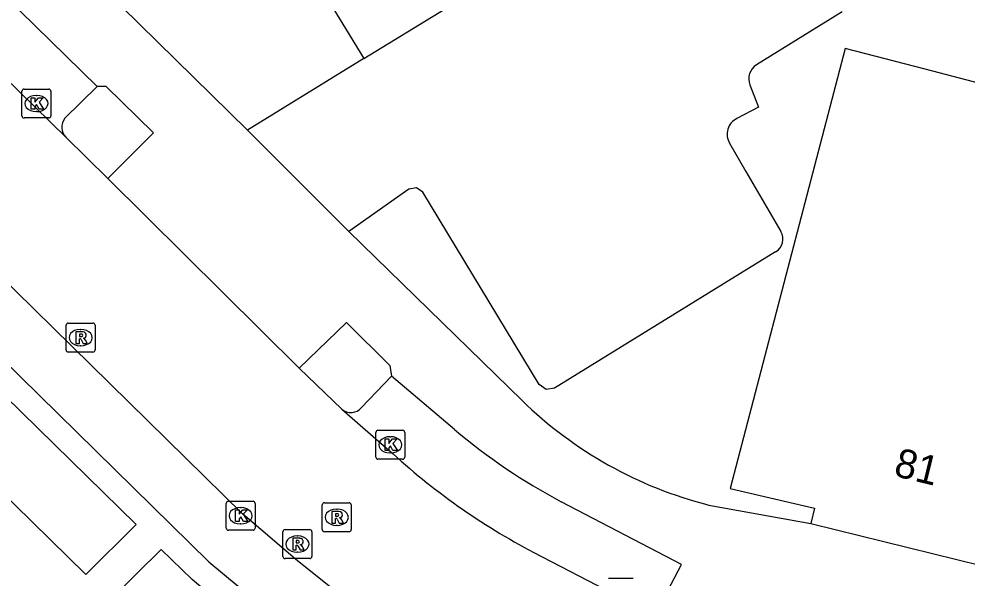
# Model space of a CAD drawing. Extents: x 159888 to 160757, y 384031 to 384746.
# Drawn here: x 160223.32 to 160256.08, y 384485.96 to 384505.27 of the extents above; entities that cross this region are included whole.
import ezdxf

# ---------------------------------------------------------------- set-up
doc = ezdxf.new("R2010")
doc.units = 0
for name, color, linetype in [('IMGEO_Kolk', 7, 'Continuous'), ('IMGEO_Pand', 7, 'Continuous'), ('IMGEO_Pand_nummerreeks', 7, 'Continuous'), ('IMGEO_Parkeervlak_open', 7, 'Continuous'), ('IMGEO_Rijbaan_lokaal_open', 7, 'Continuous'), ('IMGEO_Rioolput', 7, 'Continuous'), ('IMGEO_Voetpad_open', 7, 'Continuous')]:
    doc.layers.add(name, color=color, linetype=linetype)

msp = doc.modelspace()

# ---------------------------------------------------------------- linework, layer by layer
at = {"layer": 'IMGEO_Kolk'}
for p, q in [((160223.424, 384501.921), (160223.424, 384502.773)), ((160223.499, 384502.847), (160224.351, 384502.847)), ((160224.425, 384502.773), (160224.425, 384501.921)), ((160223.912, 384502.627), (160223.937, 384502.627)), ((160224.351, 384501.847), (160223.499, 384501.847)), ((160223.935, 384502.067), (160223.91, 384502.067)), ((160235.65, 384490.133), (160235.65, 384490.985)), ((160235.725, 384491.059), (160236.577, 384491.059)), ((160236.651, 384490.985), (160236.651, 384490.133)), ((160236.138, 384490.839), (160236.163, 384490.839)), ((160236.577, 384490.059), (160235.725, 384490.059)), ((160236.161, 384490.279), (160236.136, 384490.279)), ((160230.48, 384487.683), (160230.48, 384488.535)), ((160230.555, 384488.609), (160231.407, 384488.609)), ((160230.968, 384488.389), (160230.993, 384488.389)), ((160231.481, 384488.535), (160231.481, 384487.683)), ((160230.991, 384487.829), (160230.966, 384487.829)), ((160231.407, 384487.609), (160230.555, 384487.609)), ((160243.692, 384485.956), (160244.544, 384485.956))]:
    msp.add_line(p, q, dxfattribs=at)
for points in [[(160223.424, 384501.921), (160223.424, 384502.773)], [(160223.499, 384502.847), (160224.351, 384502.847)], [(160224.425, 384502.773), (160224.425, 384501.921)], [(160223.745, 384502.547), (160223.868, 384502.547), (160223.868, 384502.396), (160223.998, 384502.547), (160224.162, 384502.547), (160224.016, 384502.396), (160224.169, 384502.147), (160224.017, 384502.147), (160223.932, 384502.311), (160223.868, 384502.244), (160223.868, 384502.147), (160223.745, 384502.147), (160223.745, 384502.547)], [(160224.351, 384501.847), (160223.499, 384501.847)], [(160235.65, 384490.133), (160235.65, 384490.985)], [(160235.725, 384491.059), (160236.577, 384491.059)], [(160236.651, 384490.985), (160236.651, 384490.133)], [(160235.971, 384490.759), (160236.094, 384490.759), (160236.094, 384490.608), (160236.224, 384490.759), (160236.388, 384490.759), (160236.242, 384490.608), (160236.395, 384490.359), (160236.243, 384490.359), (160236.158, 384490.523), (160236.094, 384490.456), (160236.094, 384490.359), (160235.971, 384490.359), (160235.971, 384490.759)], [(160236.577, 384490.059), (160235.725, 384490.059)], [(160230.48, 384487.683), (160230.48, 384488.535)], [(160230.555, 384488.609), (160231.407, 384488.609)], [(160231.481, 384488.535), (160231.481, 384487.683)], [(160230.801, 384488.309), (160230.924, 384488.309), (160230.924, 384488.158), (160231.054, 384488.309), (160231.218, 384488.309), (160231.072, 384488.158), (160231.225, 384487.909), (160231.073, 384487.909), (160230.988, 384488.073), (160230.924, 384488.006), (160230.924, 384487.909), (160230.801, 384487.909), (160230.801, 384488.309)], [(160231.407, 384487.609), (160230.555, 384487.609)], [(160243.692, 384485.956), (160244.544, 384485.956)]]:
    msp.add_lwpolyline(points, dxfattribs=at)
for centre, start, end in [((160223.501, 384502.771), 91.552, 178.448), ((160223.501, 384502.771), 91.552, 178.448), ((160224.349, 384502.771), 1.552, 88.448), ((160224.349, 384502.771), 1.552, 88.448), ((160223.501, 384501.923), 181.552, 268.448), ((160223.501, 384501.923), 181.552, 268.448), ((160224.349, 384501.923), 271.552, 358.448), ((160224.349, 384501.923), 271.552, 358.448), ((160235.727, 384490.983), 91.552, 178.448), ((160235.727, 384490.983), 91.552, 178.448), ((160236.575, 384490.983), 1.552, 88.448), ((160236.575, 384490.983), 1.552, 88.448), ((160235.727, 384490.135), 181.552, 268.448), ((160235.727, 384490.135), 181.552, 268.448), ((160236.575, 384490.135), 271.552, 358.448), ((160236.575, 384490.135), 271.552, 358.448), ((160230.557, 384488.533), 91.552, 178.448), ((160230.557, 384488.533), 91.552, 178.448), ((160231.405, 384488.533), 1.552, 88.448), ((160231.405, 384488.533), 1.552, 88.448), ((160230.557, 384487.685), 181.552, 268.448), ((160230.557, 384487.685), 181.552, 268.448), ((160231.405, 384487.685), 271.552, 358.448), ((160231.405, 384487.685), 271.552, 358.448)]:
    msp.add_arc(centre, 0.0765, start, end, dxfattribs=at)
for centre, major_axis, ratio, start_param, end_param in [((160223.911, 384502.347), (-0.387, 0.002), 0.722429, 4.712389, 7.853982), ((160223.936, 384502.347), (-0.39, 0.002), 0.717154, 1.570796, 4.712389), ((160236.137, 384490.559), (-0.387, 0.002), 0.722429, 4.712389, 7.853982), ((160236.162, 384490.559), (-0.39, 0.002), 0.717154, 1.570796, 4.712389), ((160230.967, 384488.109), (-0.387, 0.002), 0.722429, 4.712389, 7.853982), ((160230.992, 384488.109), (-0.39, 0.002), 0.717154, 1.570796, 4.712389)]:
    msp.add_ellipse(centre, major_axis=major_axis, ratio=ratio, start_param=start_param, end_param=end_param, dxfattribs=at)
at = {"layer": 'IMGEO_Pand'}
for points in [[(160223.372, 384524.341), (160231.527, 384510.936), (160233.87, 384512.362), (160236.417, 384508.175), (160233.656, 384506.495), (160235.233, 384503.903)], [(160235.233, 384503.903), (160238.466, 384505.869), (160238.269, 384506.193), (160248.414, 384512.365)], [(160260.181, 384499.308), (160260.353, 384500), (160260.7, 384501.399), (160260.827, 384501.91), (160254.627, 384503.529), (160251.86, 384504.251), (160247.887, 384489.05), (160250.81, 384488.365), (160250.68, 384487.841)], [(160250.68, 384487.841), (160256.565, 384486.387)]]:
    msp.add_lwpolyline(points, dxfattribs=at)
at = {"layer": 'IMGEO_Parkeervlak_open'}
for points in [[(160251.757, 384505.512), (160248.804, 384503.682)], [(160235.233, 384503.903), (160231.216, 384501.429)], [(160226.022, 384502.938), (160224.91, 384501.836)], [(160248.575, 384502.993), (160248.872, 384502.218), (160248.127, 384501.832)], [(160247.87, 384500.974), (160248.438, 384500), (160249.644, 384497.93)], [(160249.464, 384497.221), (160241.821, 384492.51), (160241.53, 384492.463), (160241.292, 384492.636), (160237.275, 384499.28), (160237.052, 384499.438), (160236.785, 384499.383), (160234.712, 384497.923)], [(160236.194, 384492.935), (160235.16, 384491.842)]]:
    msp.add_lwpolyline(points, dxfattribs=at)
for centre, radius, start, end in [((160249.104, 384503.2), 0.568, 121.8653, 201.3646), ((160225.284, 384501.527), 0.485, 140.4153, 224.8617), ((160248.399, 384501.283), 0.612, 116.3246, 210.326), ((160249.193, 384497.667), 0.522, 301.2836, 30.2259), ((160234.787, 384492.173), 0.499, 230.8434, 318.4633)]:
    msp.add_arc(centre, radius, start, end, dxfattribs=at)
at = {"layer": 'IMGEO_Rijbaan_lokaal_open'}
for points in [[(160207.717, 384518.046), (160224.94, 384501.185)], [(160234.606, 384485.229), (160232.947, 384486.549), (160231.049, 384488.176), (160203.557, 384515.169)], [(160224.94, 384501.185), (160226.392, 384499.753)], [(160226.392, 384499.753), (160233.004, 384493.205)], [(160234.472, 384491.786), (160233.004, 384493.205)], [(160234.472, 384491.786), (160236.102, 384490.375)], [(160241.108, 384486.842), (160245.725, 384484.446)]]:
    msp.add_lwpolyline(points, dxfattribs=at)
msp.add_arc((160251.906, 384507.455), 23.27, 227.2222, 242.3525, dxfattribs=at)
at = {"layer": 'IMGEO_Rioolput'}
for p, q in [((160224.95, 384493.835), (160224.95, 384494.687)), ((160225.025, 384494.761), (160225.877, 384494.761)), ((160225.951, 384494.687), (160225.951, 384493.835)), ((160225.438, 384494.541), (160225.463, 384494.541)), ((160225.461, 384493.981), (160225.436, 384493.981)), ((160225.877, 384493.761), (160225.025, 384493.761)), ((160233.799, 384487.629), (160233.799, 384488.481)), ((160233.874, 384488.555), (160234.726, 384488.555)), ((160234.8, 384488.481), (160234.8, 384487.629)), ((160234.287, 384488.335), (160234.312, 384488.335)), ((160234.31, 384487.775), (160234.285, 384487.775)), ((160232.441, 384486.704), (160232.441, 384487.556)), ((160232.516, 384487.63), (160233.368, 384487.63)), ((160232.929, 384487.41), (160232.954, 384487.41)), ((160233.442, 384487.556), (160233.442, 384486.704)), ((160234.726, 384487.555), (160233.874, 384487.555)), ((160232.952, 384486.85), (160232.927, 384486.85)), ((160233.368, 384486.63), (160232.516, 384486.63))]:
    msp.add_line(p, q, dxfattribs=at)
for points in [[(160224.95, 384493.835), (160224.95, 384494.687)], [(160225.025, 384494.761), (160225.877, 384494.761)], [(160225.951, 384494.687), (160225.951, 384493.835)], [(160225.539, 384494.459), (160225.287, 384494.461), (160225.287, 384494.061)], [(160225.465, 384494.38), (160225.411, 384494.38), (160225.411, 384494.299)], [(160225.411, 384494.299), (160225.463, 384494.299)], [(160225.287, 384494.061), (160225.411, 384494.061), (160225.411, 384494.223), (160225.422, 384494.223)], [(160225.469, 384494.194), (160225.54, 384494.061), (160225.68, 384494.061), (160225.615, 384494.187)], [(160225.877, 384493.761), (160225.025, 384493.761)], [(160233.799, 384487.629), (160233.799, 384488.481)], [(160233.874, 384488.555), (160234.726, 384488.555)], [(160234.8, 384488.481), (160234.8, 384487.629)], [(160234.388, 384488.253), (160234.136, 384488.255), (160234.136, 384487.855)], [(160234.136, 384487.855), (160234.26, 384487.855), (160234.26, 384488.017), (160234.271, 384488.017)], [(160234.314, 384488.174), (160234.26, 384488.174), (160234.26, 384488.093)], [(160234.26, 384488.093), (160234.312, 384488.093)], [(160234.318, 384487.988), (160234.389, 384487.855), (160234.529, 384487.855), (160234.464, 384487.981)], [(160232.441, 384486.704), (160232.441, 384487.556)], [(160232.516, 384487.63), (160233.368, 384487.63)], [(160233.442, 384487.556), (160233.442, 384486.704)], [(160234.726, 384487.555), (160233.874, 384487.555)], [(160233.03, 384487.328), (160232.778, 384487.33), (160232.778, 384486.93)], [(160232.778, 384486.93), (160232.902, 384486.93), (160232.902, 384487.092), (160232.913, 384487.092)], [(160232.956, 384487.249), (160232.902, 384487.249), (160232.902, 384487.168)], [(160232.902, 384487.168), (160232.954, 384487.168)], [(160232.96, 384487.063), (160233.031, 384486.93), (160233.171, 384486.93), (160233.106, 384487.056)], [(160233.368, 384486.63), (160232.516, 384486.63)]]:
    msp.add_lwpolyline(points, dxfattribs=at)
for centre, radius, start, end in [((160225.027, 384494.685), 0.0765, 91.552, 178.448), ((160225.027, 384494.685), 0.0765, 91.552, 178.448), ((160225.875, 384494.685), 0.0765, 1.552, 88.448), ((160225.875, 384494.685), 0.0765, 1.552, 88.448), ((160225.447, 384494.488), 0.19, 274.7715, 282.9687), ((160225.471, 384494.284), 0.0964, 77.0061, 93.1865), ((160225.485, 384494.341), 0.0378, 276.6634, 79.6772), ((160225.538, 384494.349), 0.109, 350.3612, 89.416), ((160225.536, 384494.349), 0.112, 277.5842, 350.9817), ((160225.52, 384494.134), 0.108, 29.5134, 73.7905), ((160225.421, 384494.17), 0.0533, 26.0293, 88.6989), ((160225.027, 384493.837), 0.0765, 181.552, 268.448), ((160225.027, 384493.837), 0.0765, 181.552, 268.448), ((160225.875, 384493.837), 0.0765, 271.552, 358.448), ((160225.875, 384493.837), 0.0765, 271.552, 358.448), ((160233.876, 384488.479), 0.0765, 91.552, 178.448), ((160233.876, 384488.479), 0.0765, 91.552, 178.448), ((160234.724, 384488.479), 0.0765, 1.552, 88.448), ((160234.724, 384488.479), 0.0765, 1.552, 88.448), ((160234.27, 384487.964), 0.0533, 26.0293, 88.6989), ((160234.296, 384488.282), 0.19, 274.7715, 282.9687), ((160234.32, 384488.078), 0.0964, 77.0061, 93.1865), ((160234.334, 384488.135), 0.0378, 276.6634, 79.6772), ((160234.387, 384488.143), 0.109, 350.3612, 89.416), ((160234.385, 384488.143), 0.112, 277.5842, 350.9817), ((160234.369, 384487.928), 0.108, 29.5134, 73.7905), ((160232.518, 384487.554), 0.0765, 91.552, 178.448), ((160232.518, 384487.554), 0.0765, 91.552, 178.448), ((160233.366, 384487.554), 0.0765, 1.552, 88.448), ((160233.366, 384487.554), 0.0765, 1.552, 88.448), ((160233.876, 384487.631), 0.0765, 181.552, 268.448), ((160233.876, 384487.631), 0.0765, 181.552, 268.448), ((160234.724, 384487.631), 0.0765, 271.552, 358.448), ((160234.724, 384487.631), 0.0765, 271.552, 358.448), ((160232.912, 384487.039), 0.0533, 26.0293, 88.6989), ((160232.938, 384487.357), 0.19, 274.7715, 282.9687), ((160232.962, 384487.153), 0.0964, 77.0061, 93.1865), ((160232.976, 384487.21), 0.0378, 276.6634, 79.6772), ((160233.029, 384487.218), 0.109, 350.3612, 89.416), ((160233.027, 384487.218), 0.112, 277.5842, 350.9817), ((160233.011, 384487.003), 0.108, 29.5134, 73.7905), ((160232.518, 384486.706), 0.0765, 181.552, 268.448), ((160232.518, 384486.706), 0.0765, 181.552, 268.448), ((160233.366, 384486.706), 0.0765, 271.552, 358.448), ((160233.366, 384486.706), 0.0765, 271.552, 358.448)]:
    msp.add_arc(centre, radius, start, end, dxfattribs=at)
for centre, major_axis, ratio, start_param, end_param in [((160225.437, 384494.261), (-0.387, 0.002), 0.722429, 4.712389, 7.853982), ((160225.462, 384494.261), (-0.39, 0.002), 0.717154, 1.570796, 4.712389), ((160234.286, 384488.055), (-0.387, 0.002), 0.722429, 4.712389, 7.853982), ((160234.311, 384488.055), (-0.39, 0.002), 0.717154, 1.570796, 4.712389), ((160232.928, 384487.13), (-0.387, 0.002), 0.722429, 4.712389, 7.853982), ((160232.953, 384487.13), (-0.39, 0.002), 0.717154, 1.570796, 4.712389)]:
    msp.add_ellipse(centre, major_axis=major_axis, ratio=ratio, start_param=start_param, end_param=end_param, dxfattribs=at)
at = {"layer": 'IMGEO_Voetpad_open'}
for points in [[(160231.216, 384501.429), (160209.436, 384522.798), (160209.415, 384522.819), (160209.351, 384522.892), (160209.293, 384522.971), (160209.242, 384523.054), (160209.199, 384523.142), (160209.165, 384523.233), (160209.138, 384523.327), (160209.12, 384523.423), (160209.111, 384523.52), (160209.11, 384523.617), (160209.114, 384523.662)], [(160226.022, 384502.938), (160209.434, 384519.16)], [(160203.589, 384514.481), (160202.511, 384513.401), (160229.885, 384486.517), (160231.834, 384484.894), (160233.589, 384483.523)], [(160226.392, 384499.753), (160227.966, 384501.332), (160226.336, 384502.94), (160226.022, 384502.938)], [(160234.712, 384497.923), (160232.647, 384500), (160231.216, 384501.429)], [(160234.712, 384497.923), (160240.701, 384492.09)], [(160233.004, 384493.205), (160234.638, 384494.783), (160236.135, 384493.293), (160236.194, 384492.935)], [(160220.569, 384494.455), (160218.85, 384492.724), (160225.629, 384486.073), (160227.372, 384487.807), (160220.569, 384494.455)], [(160238.371, 384491.083), (160236.194, 384492.935)], [(160245.502, 384485.069), (160246.211, 384486.424), (160242.052, 384488.591)], [(160247.154, 384488.478), (160250.68, 384487.841)], [(160228.232, 384486.943), (160226.515, 384485.249), (160234.069, 384477.876), (160236.663, 384480.473)], [(160232.209, 384483.512), (160230.311, 384485.052), (160229.301, 384485.902), (160228.232, 384486.943)]]:
    msp.add_lwpolyline(points, dxfattribs=at)
for centre, radius, start, end in [((160250.679, 384502.346), 14.309, 225.7871, 255.7379), ((160252.112, 384507.415), 21.344, 229.9252, 241.8796)]:
    msp.add_arc(centre, radius, start, end, dxfattribs=at)

# ---------------------------------------------------------------- texts
at = {"layer": 'IMGEO_Pand_nummerreeks'}
msp.add_text('81', height=1, rotation=346.0771, dxfattribs=at).set_placement((160253.508, 384489.497))

doc.saveas('drawing.dxf')
